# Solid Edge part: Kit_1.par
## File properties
Sűrűség: 0,000 kg/m^3
Pontosság: 0,990
Author: bmolnar
Last saved by: bmolnar
Revision: 76
Username: bmolnar
Dokumentum tartalom típus: 0
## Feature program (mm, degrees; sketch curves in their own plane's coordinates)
base feature "unnamed BaseFeature 1"
sketch for "unnamed Hole 1" plane through (-28.25, 28.25, 5) normal (0, 0, -1) x-axis (0, -1, 0)
  hole centre (0, 0) bore radius 3.3235
hole "unnamed Hole 1" through
sketch for "unnamed Hole 2" plane through (-28.25, 28.25, 5) normal (0, 0, -1) x-axis (0, -1, 0)
  hole centre (56.5, 0) bore radius 3.3235
hole "unnamed Hole 2" through
sketch for "unnamed Hole 3" plane through (-28.25, 28.25, 5) normal (0, 0, -1) x-axis (0, -1, 0)
  hole centre (0, -56.5) bore radius 3.3235
hole "unnamed Hole 3" through
sketch for "unnamed Hole 4" plane through (-28.25, 28.25, 5) normal (0, 0, -1) x-axis (0, -1, 0)
  hole centre (56.5, -56.5) bore radius 3.3235
hole "unnamed Hole 4" through
pattern "unnamed Pattern 1" of "unnamed Hole 1", "unnamed Hole 2", "unnamed Hole 3", "unnamed Hole 4"
thread "unnamed Thread 1"
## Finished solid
Body 1: solid body, 295 faces, 736 edges, 457 vertices.
  Faces by surface: plane 140, cylinder 74, swept 61, cone 11, torus 8, spline 1
  Edges by curve: line 431, circle 139, spline 126, ellipse 30, curve on surface 9, intersection 1
Bounding box of the edges (mm; curved faces can reach further): 77.000 x 77.000 x 13.750, from (-38.5, -38.5, 0) to (38.5, 38.5, 13.75).
Cylindrical faces by radius (mm): R0.2 x48, R0.2008 x2, R0.2009 x2, R0.402 x1, R0.4899 x1, R2 x1, R3.3235 x4, R4.283 x1, R4.9 x4, R5.15 x4, R5.25 x4, R6 x1, R17.0898 x1
Conical faces (half-angle, radius in mm at the cone's reference point): 0.5 deg R12 x4, 0.5 deg R13.5 x2, 45 deg R3.6735 x4, 45 deg R6.25 x1
Toroidal faces (ring radius, tube radius in mm): R4.7 r0.2 x8
Planar faces by outward normal: +x 12, +y 14, +z 1, -x 15, -y 13, -z 18, oblique 67
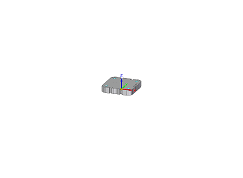
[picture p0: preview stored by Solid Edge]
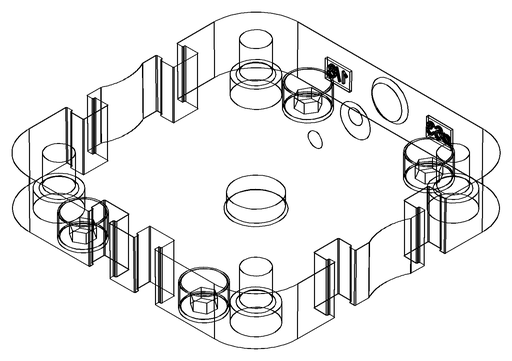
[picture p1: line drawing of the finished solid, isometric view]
